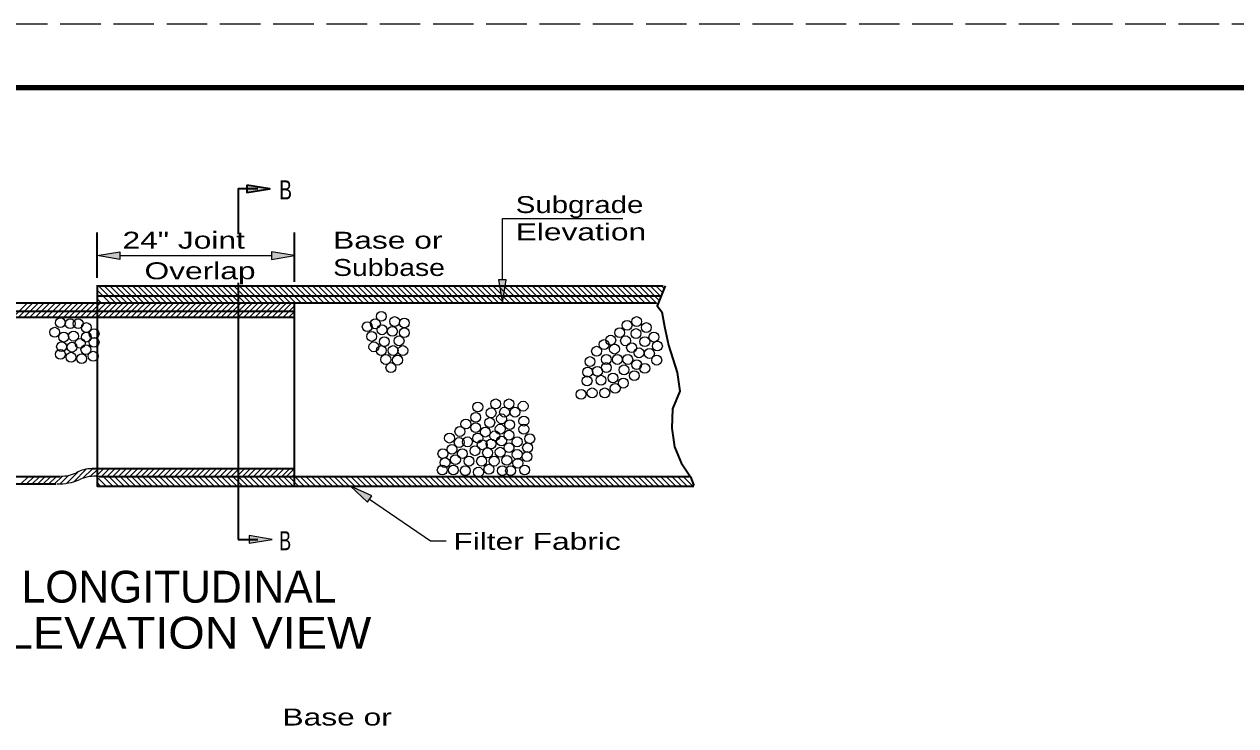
# Model space of a CAD drawing. Extents: x 36 to 71.3, y 0.3 to 22.3.
# Drawn here: x 43.4 to 52.91, y 16.82 to 22.32 of the extents above; entities that cross this region are included whole.
import ezdxf

# ---------------------------------------------------------------- set-up
doc = ezdxf.new("R2010")
doc.units = 0
doc.header["$LTSCALE"] = 0.053
doc.linetypes.add('LONG_DASHED', pattern=[7.5, 6, -1.5])
for name, color, linetype, lineweight in [('1', 7, 'Continuous', 13), ('2', 7, 'Continuous', 13), ('4', 7, 'Continuous', 13)]:
    doc.layers.add(name, color=color, linetype=linetype, lineweight=lineweight)

msp = doc.modelspace()

# ---------------------------------------------------------------- hatches: boundary and pattern name
at = {"layer": '1'}
for points in [[(44.15433, 20.53825), (44.15433, 20.47825), (43.97433, 20.50825), (43.97433, 20.50825)], [(45.34342, 20.53825), (45.34342, 20.47825), (45.52342, 20.50825), (45.52342, 20.50825)]]:
    msp.add_hatch(color=256, dxfattribs=at).paths.add_polyline_path(points)
at = {"layer": '2'}
for points in [[(45.15092, 21.06208), (45.15092, 21.00208), (45.33092, 21.03208), (45.33092, 21.03208)], [(47.186, 20.31667), (47.12608, 20.31667), (47.15608, 20.13667), (47.15608, 20.13667)], [(46.09625, 18.57242), (46.13017, 18.62192), (45.96475, 18.699), (45.96475, 18.699)], [(45.16858, 18.31033), (45.16858, 18.25033), (45.34858, 18.28033), (45.34858, 18.28033)]]:
    msp.add_hatch(color=256, dxfattribs=at).paths.add_polyline_path(points)

# ---------------------------------------------------------------- linework, layer by layer
at = {"layer": '1', "linetype": 'LONG_DASHED', "lineweight": 25}
msp.add_line((71.17325, 22.32408), (35.97325, 22.32408), dxfattribs=at)
at = {"layer": '1', "lineweight": 158}
for p, q in [((52.503, 21.82408), (38.58992, 21.82408)), ((65.01858, 21.82408), (52.503, 21.82408))]:
    msp.add_line(p, q, dxfattribs=at)
at = {"layer": '1', "lineweight": 35}
for p, q in [((43.97433, 20.33217), (43.97433, 20.68825)), ((45.52342, 20.30183), (45.52342, 20.68825)), ((43.96925, 20.26967), (48.41833, 20.26967)), ((43.98, 20.19108), (48.39242, 20.19108)), ((40.6925, 20.13667), (48.36025, 20.13667)), ((40.70233, 20.07117), (45.51333, 20.07117)), ((45.52225, 20.1275), (45.52225, 18.6995)), ((40.71125, 20.024), (45.51333, 20.024)), ((45.51692, 18.83508), (43.93617, 18.83508)), ((43.68442, 18.77233), (40.88925, 18.77233)), ((43.99067, 18.77483), (48.623, 18.77483)), ((43.65142, 18.7125), (40.85458, 18.7125))]:
    msp.add_line(p, q, dxfattribs=at)
at = {"layer": '1', "lineweight": 25}
for p, q in [((44.15433, 20.50825), (45.34342, 20.50825)), ((44.11908, 20.13667), (43.98608, 20.26967)), ((44.16325, 20.13667), (44.03025, 20.26967)), ((44.20742, 20.13667), (44.0745, 20.26967)), ((44.25167, 20.13667), (44.11867, 20.26967)), ((44.29583, 20.13667), (44.16283, 20.26967)), ((44.34, 20.13667), (44.20708, 20.26967)), ((44.38425, 20.13667), (44.25125, 20.26967)), ((44.42842, 20.13667), (44.29542, 20.26967)), ((44.47258, 20.13667), (44.33967, 20.26967)), ((44.51683, 20.13667), (44.38383, 20.26967)), ((44.561, 20.13667), (44.428, 20.26967)), ((44.60517, 20.13667), (44.47225, 20.26967)), ((44.64942, 20.13667), (44.51642, 20.26967)), ((44.69358, 20.13667), (44.56058, 20.26967)), ((44.73775, 20.13667), (44.60483, 20.26967)), ((44.782, 20.13667), (44.649, 20.26967)), ((44.82617, 20.13667), (44.69317, 20.26967)), ((44.87033, 20.13667), (44.73733, 20.26967)), ((44.9145, 20.13667), (44.78158, 20.26967)), ((44.95875, 20.13667), (44.82575, 20.26967)), ((45.00292, 20.13667), (44.86992, 20.26967)), ((45.04708, 20.13667), (44.91417, 20.26967)), ((45.09133, 20.13667), (44.95833, 20.26967)), ((45.1355, 20.13667), (45.0025, 20.26967)), ((45.17967, 20.13667), (45.04675, 20.26967)), ((45.22392, 20.13667), (45.09092, 20.26967)), ((45.26808, 20.13667), (45.13508, 20.26967)), ((45.31225, 20.13667), (45.17933, 20.26967)), ((45.3565, 20.13667), (45.2235, 20.26967)), ((45.40067, 20.13667), (45.26767, 20.26967)), ((45.44483, 20.13667), (45.31192, 20.26967)), ((45.48908, 20.13667), (45.35608, 20.26967)), ((45.53325, 20.13667), (45.40025, 20.26967)), ((45.57742, 20.13667), (45.4445, 20.26967)), ((45.62167, 20.13667), (45.48867, 20.26967)), ((45.66583, 20.13667), (45.53283, 20.26967)), ((45.71, 20.13667), (45.57708, 20.26967)), ((45.75425, 20.13667), (45.62125, 20.26967)), ((45.79842, 20.13667), (45.66542, 20.26967)), ((45.84258, 20.13667), (45.70967, 20.26967)), ((45.88683, 20.13667), (45.75383, 20.26967)), ((45.931, 20.13667), (45.798, 20.26967)), ((45.97517, 20.13667), (45.84225, 20.26967)), ((46.01942, 20.13667), (45.88642, 20.26967)), ((46.06358, 20.13667), (45.93058, 20.26967)), ((46.10775, 20.13667), (45.97483, 20.26967)), ((46.152, 20.13667), (46.019, 20.26967)), ((46.19617, 20.13667), (46.06317, 20.26967)), ((46.24033, 20.13667), (46.10742, 20.26967)), ((46.28458, 20.13667), (46.15158, 20.26967)), ((46.32875, 20.13667), (46.19575, 20.26967)), ((46.37292, 20.13667), (46.24, 20.26967)), ((46.41717, 20.13667), (46.28417, 20.26967)), ((46.46133, 20.13667), (46.32833, 20.26967)), ((46.5055, 20.13667), (46.37258, 20.26967)), ((46.54975, 20.13667), (46.41675, 20.26967)), ((46.59392, 20.13667), (46.46092, 20.26967)), ((46.63808, 20.13667), (46.50517, 20.26967)), ((46.68233, 20.13667), (46.54933, 20.26967)), ((46.7265, 20.13667), (46.5935, 20.26967)), ((46.77067, 20.13667), (46.63775, 20.26967)), ((46.81492, 20.13667), (46.68192, 20.26967)), ((46.85908, 20.13667), (46.72608, 20.26967)), ((46.90325, 20.13667), (46.77033, 20.26967)), ((46.9475, 20.13667), (46.8145, 20.26967)), ((46.99167, 20.13667), (46.85867, 20.26967)), ((47.03583, 20.13667), (46.90292, 20.26967)), ((47.08008, 20.13667), (46.94708, 20.26967)), ((47.12425, 20.13667), (46.99125, 20.26967)), ((47.16842, 20.13667), (47.0355, 20.26967)), ((47.21267, 20.13667), (47.07967, 20.26967)), ((47.25683, 20.13667), (47.12383, 20.26967)), ((47.301, 20.13667), (47.16808, 20.26967)), ((47.34525, 20.13667), (47.21225, 20.26967)), ((47.38942, 20.13667), (47.25642, 20.26967)), ((47.43358, 20.13667), (47.30067, 20.26967)), ((47.47783, 20.13667), (47.34483, 20.26967)), ((47.522, 20.13667), (47.389, 20.26967)), ((47.56617, 20.13667), (47.43325, 20.26967)), ((47.61042, 20.13667), (47.47742, 20.26967)), ((47.65458, 20.13667), (47.52158, 20.26967)), ((47.69875, 20.13667), (47.56583, 20.26967)), ((47.743, 20.13667), (47.61, 20.26967)), ((47.78717, 20.13667), (47.65417, 20.26967)), ((47.83133, 20.13667), (47.69842, 20.26967)), ((47.87558, 20.13667), (47.74258, 20.26967)), ((47.91975, 20.13667), (47.78675, 20.26967)), ((47.96392, 20.13667), (47.831, 20.26967)), ((48.00817, 20.13667), (47.87517, 20.26967)), ((48.05233, 20.13667), (47.91933, 20.26967)), ((48.0965, 20.13667), (47.96358, 20.26967)), ((48.14075, 20.13667), (48.00775, 20.26967)), ((48.18492, 20.13667), (48.05192, 20.26967)), ((48.22908, 20.13667), (48.09617, 20.26967)), ((48.27333, 20.13667), (48.14033, 20.26967)), ((48.3175, 20.13667), (48.1845, 20.26967)), ((48.37508, 20.12333), (48.22875, 20.26967)), ((48.38767, 20.15492), (48.27292, 20.26967)), ((48.40033, 20.18642), (48.31708, 20.26967)), ((48.41292, 20.218), (48.36133, 20.26967)), ((48.4255, 20.24958), (48.4055, 20.26967)), ((44.07483, 20.13667), (43.97433, 20.23717)), ((44.00633, 20.13667), (43.97433, 20.16867)), ((43.31458, 20.024), (43.42725, 20.13667)), ((43.35875, 20.024), (43.47142, 20.13667)), ((43.40292, 20.024), (43.51558, 20.13667)), ((43.44717, 20.024), (43.55983, 20.13667)), ((43.49133, 20.024), (43.604, 20.13667)), ((43.5355, 20.024), (43.64817, 20.13667)), ((43.57975, 20.024), (43.69242, 20.13667)), ((43.62392, 20.024), (43.73658, 20.13667)), ((43.66808, 20.024), (43.78075, 20.13667)), ((43.71233, 20.024), (43.825, 20.13667)), ((43.7565, 20.024), (43.86917, 20.13667)), ((43.80067, 20.024), (43.91333, 20.13667)), ((43.84492, 20.024), (43.95758, 20.13667)), ((43.88908, 20.024), (44.00175, 20.13667)), ((43.93325, 20.024), (44.04592, 20.13667)), ((43.9775, 20.024), (44.09017, 20.13667)), ((44.02167, 20.024), (44.13433, 20.13667)), ((44.06583, 20.024), (44.1785, 20.13667)), ((44.11008, 20.024), (44.22275, 20.13667)), ((44.15425, 20.024), (44.26692, 20.13667)), ((44.19842, 20.024), (44.31108, 20.13667)), ((44.24267, 20.024), (44.35533, 20.13667)), ((44.28683, 20.024), (44.3995, 20.13667)), ((44.331, 20.024), (44.44367, 20.13667)), ((44.37525, 20.024), (44.48792, 20.13667)), ((44.41942, 20.024), (44.53208, 20.13667)), ((44.46358, 20.024), (44.57625, 20.13667)), ((44.50783, 20.024), (44.6205, 20.13667)), ((44.552, 20.024), (44.66467, 20.13667)), ((44.59617, 20.024), (44.70883, 20.13667)), ((44.64042, 20.024), (44.75308, 20.13667)), ((44.68458, 20.024), (44.79725, 20.13667)), ((44.72875, 20.024), (44.84142, 20.13667)), ((44.773, 20.024), (44.88567, 20.13667)), ((44.81717, 20.024), (44.92983, 20.13667)), ((44.86133, 20.024), (44.974, 20.13667)), ((44.90558, 20.024), (45.01825, 20.13667)), ((44.94975, 20.024), (45.06242, 20.13667)), ((44.99392, 20.024), (45.10658, 20.13667)), ((45.03817, 20.024), (45.15083, 20.13667)), ((45.08233, 20.024), (45.195, 20.13667)), ((45.1265, 20.024), (45.23917, 20.13667)), ((45.17075, 20.024), (45.28342, 20.13667)), ((45.21492, 20.024), (45.32758, 20.13667)), ((45.25908, 20.024), (45.37175, 20.13667)), ((45.30333, 20.024), (45.416, 20.13667)), ((45.3475, 20.024), (45.46017, 20.13667)), ((45.39167, 20.024), (45.50433, 20.13667)), ((45.43592, 20.024), (45.52225, 20.11042)), ((45.48008, 20.024), (45.52225, 20.06625)), ((43.79083, 18.7325), (43.88992, 18.83158)), ((43.86267, 18.76017), (43.93758, 18.83508)), ((43.92075, 18.774), (43.98183, 18.83508)), ((43.96692, 18.776), (44.026, 18.83508)), ((44.00992, 18.77483), (44.07017, 18.83508)), ((44.05417, 18.77483), (44.11442, 18.83508)), ((44.09833, 18.77483), (44.15858, 18.83508)), ((44.1425, 18.77483), (44.20275, 18.83508)), ((44.18675, 18.77483), (44.247, 18.83508)), ((44.23092, 18.77483), (44.29117, 18.83508)), ((44.27508, 18.77483), (44.33533, 18.83508)), ((44.31933, 18.77483), (44.37958, 18.83508)), ((44.3635, 18.77483), (44.42375, 18.83508)), ((44.40767, 18.77483), (44.46792, 18.83508)), ((44.45192, 18.77483), (44.51217, 18.83508)), ((44.49608, 18.77483), (44.55633, 18.83508)), ((44.54025, 18.77483), (44.6005, 18.83508)), ((44.5845, 18.77483), (44.64475, 18.83508)), ((44.62867, 18.77483), (44.68892, 18.83508)), ((44.67283, 18.77483), (44.73308, 18.83508)), ((44.71708, 18.77483), (44.77733, 18.83508)), ((44.76125, 18.77483), (44.8215, 18.83508)), ((44.80542, 18.77483), (44.86567, 18.83508)), ((44.84967, 18.77483), (44.90992, 18.83508)), ((44.89383, 18.77483), (44.95408, 18.83508)), ((44.938, 18.77483), (44.99825, 18.83508)), ((44.98225, 18.77483), (45.0425, 18.83508)), ((45.02642, 18.77483), (45.08667, 18.83508)), ((45.07058, 18.77483), (45.13083, 18.83508)), ((45.11483, 18.77483), (45.17508, 18.83508)), ((45.159, 18.77483), (45.21925, 18.83508)), ((45.20317, 18.77483), (45.26342, 18.83508)), ((45.24742, 18.77483), (45.30767, 18.83508)), ((45.29158, 18.77483), (45.35183, 18.83508)), ((45.33575, 18.77483), (45.396, 18.83508)), ((45.37992, 18.77483), (45.44025, 18.83508)), ((45.42417, 18.77483), (45.48442, 18.83508)), ((45.46208, 18.77483), (45.52242, 18.83508)), ((43.37308, 18.7125), (43.43292, 18.77233)), ((43.41725, 18.7125), (43.47708, 18.77233)), ((43.4615, 18.7125), (43.52125, 18.77233)), ((43.50567, 18.7125), (43.5655, 18.77233)), ((43.54983, 18.7125), (43.60967, 18.77233)), ((43.59408, 18.7125), (43.65383, 18.77233)), ((43.63825, 18.7125), (43.70225, 18.77658)), ((43.68575, 18.71583), (43.75317, 18.78325)), ((43.73408, 18.72), (43.82308, 18.80892)), ((44.04658, 18.699), (43.97083, 18.77483)), ((44.09825, 18.699), (44.0225, 18.77483)), ((44.1425, 18.699), (44.06667, 18.77483)), ((44.18667, 18.699), (44.11083, 18.77483)), ((44.23083, 18.699), (44.15508, 18.77483)), ((44.27508, 18.699), (44.19925, 18.77483)), ((44.31925, 18.699), (44.24342, 18.77483)), ((44.36342, 18.699), (44.28767, 18.77483)), ((44.40767, 18.699), (44.33183, 18.77483)), ((44.45183, 18.699), (44.376, 18.77483)), ((44.496, 18.699), (44.42025, 18.77483)), ((44.54025, 18.699), (44.46442, 18.77483)), ((44.58442, 18.699), (44.50858, 18.77483)), ((44.62858, 18.699), (44.55283, 18.77483)), ((44.67283, 18.699), (44.597, 18.77483)), ((44.717, 18.699), (44.64117, 18.77483)), ((44.76117, 18.699), (44.68542, 18.77483)), ((44.80542, 18.699), (44.72958, 18.77483)), ((44.84958, 18.699), (44.77375, 18.77483)), ((44.89375, 18.699), (44.818, 18.77483)), ((44.938, 18.699), (44.86217, 18.77483)), ((44.98217, 18.699), (44.90633, 18.77483)), ((45.02633, 18.699), (44.95058, 18.77483)), ((45.07058, 18.699), (44.99475, 18.77483)), ((45.11475, 18.699), (45.03892, 18.77483)), ((45.15892, 18.699), (45.08317, 18.77483)), ((45.20317, 18.699), (45.12733, 18.77483)), ((45.24733, 18.699), (45.1715, 18.77483)), ((45.2915, 18.699), (45.21575, 18.77483)), ((45.33575, 18.699), (45.25992, 18.77483)), ((45.37992, 18.699), (45.30408, 18.77483)), ((45.42408, 18.699), (45.34825, 18.77483)), ((45.46833, 18.699), (45.3925, 18.77483)), ((45.5125, 18.699), (45.43667, 18.77483)), ((45.55667, 18.699), (45.48083, 18.77483)), ((45.50633, 18.77483), (45.52225, 18.79083)), ((45.60092, 18.699), (45.51567, 18.78425)), ((45.64508, 18.699), (45.56925, 18.77483)), ((45.68925, 18.699), (45.61342, 18.77483)), ((45.7335, 18.699), (45.65767, 18.77483)), ((45.77767, 18.699), (45.70183, 18.77483)), ((45.82183, 18.699), (45.746, 18.77483)), ((45.86608, 18.699), (45.79025, 18.77483)), ((45.91025, 18.699), (45.83442, 18.77483)), ((45.95442, 18.699), (45.87858, 18.77483)), ((45.99867, 18.699), (45.92283, 18.77483)), ((46.04283, 18.699), (45.967, 18.77483)), ((46.087, 18.699), (46.01117, 18.77483)), ((46.13125, 18.699), (46.05542, 18.77483)), ((46.17542, 18.699), (46.09958, 18.77483)), ((46.21958, 18.699), (46.14375, 18.77483)), ((46.26383, 18.699), (46.188, 18.77483)), ((46.308, 18.699), (46.23217, 18.77483)), ((46.35217, 18.699), (46.27633, 18.77483)), ((46.39642, 18.699), (46.32058, 18.77483)), ((46.44058, 18.699), (46.36475, 18.77483)), ((46.48475, 18.699), (46.40892, 18.77483)), ((46.529, 18.699), (46.45317, 18.77483)), ((46.57317, 18.699), (46.49733, 18.77483)), ((46.61733, 18.699), (46.5415, 18.77483)), ((46.66158, 18.699), (46.58575, 18.77483)), ((46.70575, 18.699), (46.62992, 18.77483)), ((46.74992, 18.699), (46.67408, 18.77483)), ((46.79417, 18.699), (46.71833, 18.77483)), ((46.83833, 18.699), (46.7625, 18.77483)), ((46.8825, 18.699), (46.80667, 18.77483)), ((46.92667, 18.699), (46.85092, 18.77483)), ((46.97092, 18.699), (46.89508, 18.77483)), ((47.01508, 18.699), (46.93925, 18.77483)), ((47.05925, 18.699), (46.9835, 18.77483)), ((47.1035, 18.699), (47.02767, 18.77483)), ((47.14767, 18.699), (47.07183, 18.77483)), ((47.19183, 18.699), (47.11608, 18.77483)), ((47.23608, 18.699), (47.16025, 18.77483)), ((47.28025, 18.699), (47.20442, 18.77483)), ((47.32442, 18.699), (47.24867, 18.77483)), ((47.36867, 18.699), (47.29283, 18.77483)), ((47.41283, 18.699), (47.337, 18.77483)), ((47.457, 18.699), (47.38125, 18.77483)), ((47.50125, 18.699), (47.42542, 18.77483)), ((47.54542, 18.699), (47.46958, 18.77483)), ((47.58958, 18.699), (47.51383, 18.77483)), ((47.63383, 18.699), (47.558, 18.77483)), ((47.678, 18.699), (47.60217, 18.77483)), ((47.72217, 18.699), (47.64642, 18.77483)), ((47.76642, 18.699), (47.69058, 18.77483)), ((47.81058, 18.699), (47.73475, 18.77483)), ((47.85475, 18.699), (47.779, 18.77483)), ((47.899, 18.699), (47.82317, 18.77483)), ((47.94317, 18.699), (47.86733, 18.77483)), ((47.98733, 18.699), (47.91158, 18.77483)), ((48.03158, 18.699), (47.95575, 18.77483)), ((48.07575, 18.699), (47.99992, 18.77483)), ((48.11992, 18.699), (48.04417, 18.77483)), ((48.16417, 18.699), (48.08833, 18.77483)), ((48.20833, 18.699), (48.1325, 18.77483)), ((48.2525, 18.699), (48.17675, 18.77483)), ((48.29675, 18.699), (48.22092, 18.77483)), ((48.34092, 18.699), (48.26508, 18.77483)), ((48.38508, 18.699), (48.30933, 18.77483)), ((48.42933, 18.699), (48.3535, 18.77483)), ((48.4735, 18.699), (48.39767, 18.77483)), ((48.51767, 18.699), (48.44192, 18.77483)), ((48.56192, 18.699), (48.48608, 18.77483)), ((48.60608, 18.699), (48.53025, 18.77483)), ((48.65025, 18.699), (48.5745, 18.77483)), ((44.00242, 18.699), (43.97433, 18.72708))]:
    msp.add_line(p, q, dxfattribs=at)
at = {"layer": '1'}
for points in [[(44.15433, 20.53825), (44.15433, 20.47825), (43.97433, 20.50825), (43.97433, 20.50825)], [(45.34342, 20.53825), (45.34342, 20.47825), (45.52342, 20.50825), (45.52342, 20.50825)]]:
    msp.add_lwpolyline(points, close=True, dxfattribs=at)
at = {"layer": '1', "lineweight": 35}
for points in [[(43.97433, 20.27017), (43.97433, 18.699), (48.65825, 18.699)], [(48.4335, 20.26967), (48.371, 20.11308), (48.40758, 20.06592), (48.42817, 19.95133), (48.46033, 19.80525), (48.52825, 19.591), (48.54883, 19.44492), (48.49158, 19.30408), (48.48625, 19.15217), (48.50683, 19.00608), (48.5595, 18.881), (48.63192, 18.77158), (48.65875, 18.70342)]]:
    msp.add_lwpolyline(points, dxfattribs=at)
at = {"layer": '1', "lineweight": 25}
for centre in [(46.20608, 20.031), (43.687, 19.98133), (43.76342, 19.97375), (43.82592, 19.97375), (43.89017, 19.94317), (46.095, 19.94958), (46.15925, 19.97242), (46.31025, 19.99025), (46.38667, 19.97883), (48.13492, 19.961), (48.20958, 19.99025), (48.28592, 19.94317), (43.64183, 19.90625), (43.71308, 19.86808), (43.78942, 19.87575), (43.89017, 19.86808), (43.95092, 19.89483), (46.12967, 19.87317), (46.21133, 19.92533), (46.29292, 19.91392), (46.345, 19.83883), (46.38667, 19.90242), (48.00642, 19.84392), (48.07592, 19.90242), (48.12275, 19.83883), (48.20433, 19.89608), (48.345, 19.86808), (43.69567, 19.793), (43.77725, 19.78917), (43.8415, 19.81975), (43.88667, 19.77008), (43.95092, 19.82733), (46.14708, 19.79175), (46.20608, 19.7625), (46.22867, 19.83242), (46.29808, 19.7625), (46.3745, 19.7625), (47.89533, 19.75733), (47.95433, 19.80958), (48.03592, 19.77392), (48.16967, 19.78533), (48.22867, 19.74467), (48.27375, 19.83242), (48.37275, 19.79808), (43.687, 19.73317), (43.77033, 19.71025), (43.85367, 19.69883), (43.94392, 19.71792), (46.24083, 19.6925), (46.33283, 19.68733), (47.84325, 19.67592), (47.97175, 19.6925), (48.0585, 19.6925), (48.14008, 19.6925), (48.20958, 19.65175), (48.31025, 19.73958), (48.3675, 19.68733), (47.82592, 19.59317), (47.90225, 19.59958), (47.97175, 19.62883), (48.11058, 19.611), (48.19217, 19.56517), (48.27375, 19.6225), (47.82067, 19.5245), (47.93008, 19.52958), (48.02383, 19.54742), (48.04117, 19.46592), (48.10542, 19.50667), (47.77383, 19.41883), (47.86058, 19.43033), (47.95958, 19.43033), (46.963, 19.31958), (47.06717, 19.27375), (47.10367, 19.34375), (47.17308, 19.27883), (47.20783, 19.34375), (47.25467, 19.27883), (47.31892, 19.32592), (46.86925, 19.18592), (46.94567, 19.23817), (47.05675, 19.19742), (47.14883, 19.22667), (47.213, 19.18083), (47.32417, 19.20883), (46.82242, 19.12742), (46.94567, 19.15667), (47.02208, 19.12233), (47.09675, 19.09308), (47.13842, 19.14525), (47.20783, 19.09817), (47.32417, 19.14525), (46.74083, 19.07525), (46.75992, 18.98742), (46.81717, 19.04083), (46.88142, 19.04592), (46.963, 19.07525), (46.99775, 19.02308), (47.06717, 19.02942), (47.14883, 19.05233), (47.20783, 19.00017), (47.27208, 19.04592), (47.35367, 19.00017), (46.68875, 18.95308), (46.78767, 18.906), (46.8415, 18.95308), (46.89358, 18.8945), (46.9405, 18.97592), (46.99258, 18.8945), (47.03942, 18.95942), (47.0915, 18.8945), (47.13842, 18.9645), (47.1905, 18.90083), (47.27208, 18.94667), (47.34842, 18.93017), (46.6835, 18.8245), (46.70608, 18.88308), (46.77033, 18.8245), (46.86408, 18.81942), (47.04983, 18.83083), (47.15575, 18.81942), (47.22, 18.81942), (47.27725, 18.878), (47.33108, 18.8245)]:
    msp.add_circle(centre, 0.03866, dxfattribs=at)
at = {"layer": '1'}
for centre in [(46.28075, 19.62883), (47.371, 19.07017), (46.96825, 18.808)]:
    msp.add_circle(centre, 0.03866, dxfattribs=at)
at = {"layer": '1', "lineweight": 25}
for centre, radius, start, end in [((43.9305, 18.602), 0.23321, 89.01851, 120.60609), ((43.6755, 19.12033), 0.40463, 267.73033, 293.88752), ((43.687, 19.08983), 0.31366, 270.37706, 293.44541), ((43.95592, 18.49792), 0.27836, 83.36029, 114.60008)]:
    msp.add_arc(centre, radius, start, end, dxfattribs=at)
at = {"layer": '2', "lineweight": 35}
for p, q in [((45.08208, 21.03567), (45.08208, 20.67725)), ((45.23592, 21.033), (45.08208, 21.033)), ((45.08208, 20.29467), (45.08208, 18.28033)), ((45.08208, 18.28033), (45.23592, 18.28033))]:
    msp.add_line(p, q, dxfattribs=at)
msp.add_lwpolyline([(45.15092, 21.06208), (45.15092, 21.00208), (45.33092, 21.03208), (45.33092, 21.03208)], close=True, dxfattribs=at)
at = {"layer": '2', "lineweight": 25}
for points in [[(47.15608, 20.31667), (47.15608, 20.79917), (48.10092, 20.79917)], [(46.11317, 18.59717), (46.5915, 18.26892), (46.71475, 18.26892)]]:
    msp.add_lwpolyline(points, dxfattribs=at)
at = {"layer": '2'}
for points in [[(47.186, 20.31667), (47.12608, 20.31667), (47.15608, 20.13667), (47.15608, 20.13667)], [(46.09625, 18.57242), (46.13017, 18.62192), (45.96475, 18.699), (45.96475, 18.699)], [(45.16858, 18.31033), (45.16858, 18.25033), (45.34858, 18.28033), (45.34858, 18.28033)]]:
    msp.add_lwpolyline(points, close=True, dxfattribs=at)
at = {"layer": '4'}
msp.add_line((45.52342, 20.50825), (45.5235, 20.50825), dxfattribs=at)
at = {"layer": '4', "lineweight": 25}
for p, q in [((43.97433, 20.26967), (43.97442, 20.26967)), ((45.52342, 20.23933), (45.5235, 20.23933))]:
    msp.add_line(p, q, dxfattribs=at)

# ---------------------------------------------------------------- texts
at = {"layer": '2'}
for s, height, width, p in [('B', 0.15, 0.75, (45.40417, 20.94875)), ('Subgrade', 0.133, 1.3, (47.26033, 20.84192)), ('Elevation', 0.133, 1.4, (47.26033, 20.62758)), ('24" Joint', 0.133, 1.4, (44.17392, 20.56233)), ('Base or', 0.133, 1.4, (45.82725, 20.56233)), ('Overlap', 0.133, 1.4, (44.34667, 20.32217)), ('Subbase', 0.133, 1.25, (45.82725, 20.34808)), ('B', 0.15, 0.7, (45.40417, 18.19475)), ('Filter Fabric', 0.133, 1.4, (46.77092, 18.19825)), ('ELEVATION VIEW', 0.25, 1.1, (43.02083, 17.422)), ('Base or', 0.133, 1.4, (45.42967, 16.81908))]:
    msp.add_text(s, height=height, dxfattribs=dict(at, width=width)).set_placement(p)
msp.add_text('LONGITUDINAL', height=0.25, dxfattribs=at).set_placement((43.38225, 17.78358))

doc.saveas('drawing.dxf')
